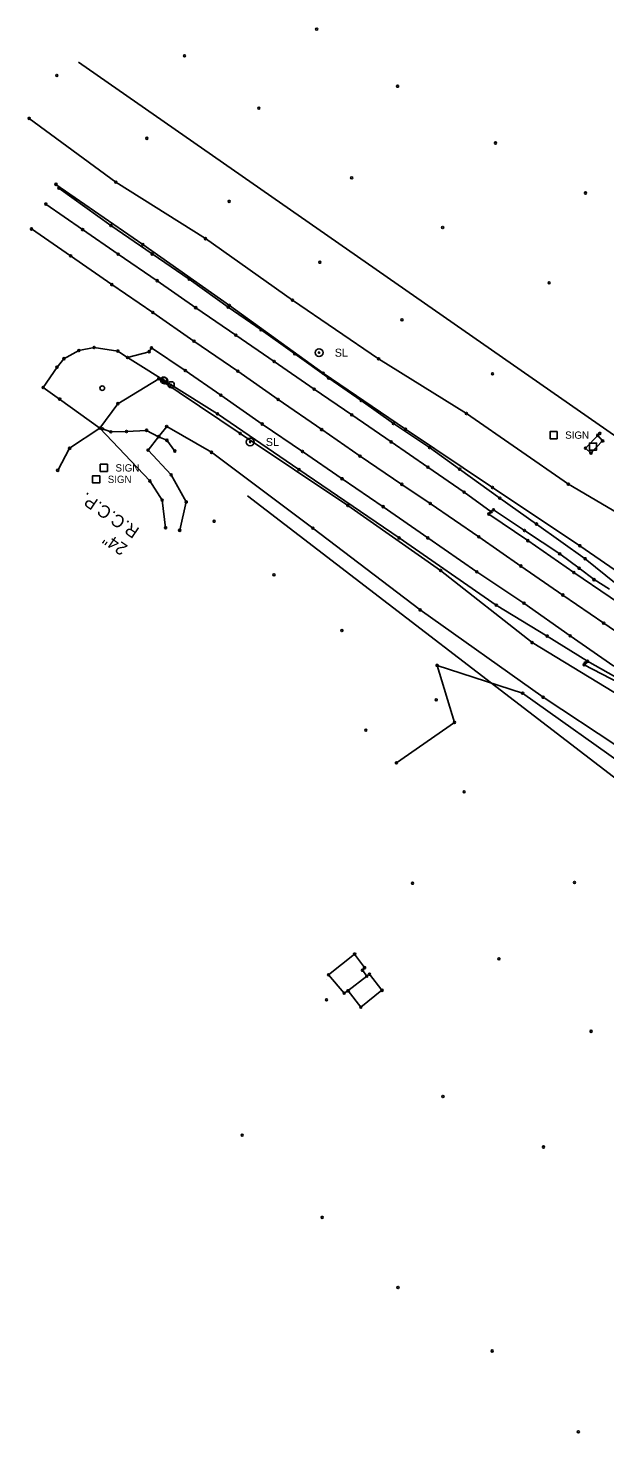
# Model space of a CAD drawing. Extents: x 15502398 to 15534190, y 8766930 to 8782112.
# Drawn here: x 15514537 to 15514815, y 8778797 to 8779472 of the extents above; entities that cross this region are included whole.
import ezdxf

# ---------------------------------------------------------------- set-up
doc = ezdxf.new("R2010")
doc.units = 0
for name, color, linetype in [('Default', 7, 'Continuous'), ('dsnCellElements', 7, 'Continuous'), ('EXT_BL', 7, 'Continuous'), ('EXT_C', 7, 'Continuous'), ('EXT_D', 7, 'Continuous'), ('EXT_EP', 7, 'Continuous'), ('EXT_SH', 7, 'Continuous'), ('EXT_SNP', 7, 'Continuous'), ('Fence', 7, 'Continuous'), ('Natural', 7, 'Continuous'), ('SurControl', 7, 'Continuous'), ('SurPointsNonDTM', 7, 'Continuous'), ('SurRoadPoints', 7, 'Continuous'), ('SurSurveyPoints', 7, 'Continuous'), ('Text', 7, 'Continuous')]:
    doc.layers.add(name, color=color, linetype=linetype)

msp = doc.modelspace()

# ---------------------------------------------------------------- linework, layer by layer
at = {"layer": 'Default'}
for p, q in [((15514602.6, 8779303.23), (15514602.6, 8779303.23)), ((15514603.07, 8779302.94), (15514603.07, 8779302.94)), ((15514606.2, 8779300.99), (15514606.2, 8779300.99)), ((15514680.96, 8779015.24), (15514680.96, 8779015.24))]:
    msp.add_line(p, q, dxfattribs=at)
msp.add_lwpolyline([(15514805.39, 8779167.3), (15514804.8, 8779166.43), (15514817.44, 8779159.8), (15514834.09, 8779151.41), (15514850.59, 8779142.29), (15514866.26, 8779132.25), (15514876.21, 8779125.21)], dxfattribs=at)
at = {"layer": 'dsnCellElements'}
for centre, radius in [((15514677.34, 8779316.44), 1.88), ((15514677.34, 8779316.44), 0.314), ((15514644.18, 8779273.47), 1.88), ((15514644.18, 8779273.47), 0.314)]:
    msp.add_circle(centre, radius, dxfattribs=at)
at = {"layer": 'EXT_BL'}
for points in [[(15514537.87, 8779429.04), (15514579.54, 8779398.37), (15514622.66, 8779371.23), (15514664.5, 8779341.66), (15514705.97, 8779313.45), (15514748.18, 8779287.18), (15514797.21, 8779253.2), (15514839.32, 8779228.6)], [(15514853.31, 8779188.82), (15514802.74, 8779223.63), (15514760.78, 8779251.63), (15514718.91, 8779279.58), (15514679.29, 8779306.58), (15514634.17, 8779339.1), (15514592.6, 8779368.4), (15514550.78, 8779397.34)], [(15514603.51, 8779232.29), (15514601.83, 8779245.57), (15514595.97, 8779254.75), (15514571.89, 8779280.15), (15514580.49, 8779291.91), (15514600.21, 8779303.93), (15514639.34, 8779277.58), (15514691.14, 8779242.93), (15514735.8, 8779211.77), (15514779.77, 8779177.06), (15514822.79, 8779150.92), (15514868.05, 8779125.45), (15514870.51, 8779121.99), (15514877.23, 8779120.79), (15514891.1, 8779108.56)], [(15514891.1, 8779108.56), (15514871.59, 8779095.57), (15514820.49, 8779127.42), (15514785.11, 8779150.78), (15514725.93, 8779192.76), (15514674.35, 8779232.07), (15514625.56, 8779268.53), (15514604.03, 8779280.96), (15514600.16, 8779276.05), (15514595.07, 8779269.61), (15514606.22, 8779257.75), (15514613.46, 8779244.67), (15514610.28, 8779231.05)]]:
    msp.add_lwpolyline(points, dxfattribs=at)
at = {"layer": 'EXT_C'}
msp.add_lwpolyline([(15514539.01, 8779375.88), (15514557.84, 8779363.02), (15514577.62, 8779349.14), (15514597.39, 8779335.77), (15514617.16, 8779321.93), (15514638.22, 8779307.5), (15514657.64, 8779293.96), (15514678.58, 8779279.44), (15514697.02, 8779266.72), (15514717.08, 8779253.14), (15514730.81, 8779243.96), (15514754.17, 8779227.88), (15514774.39, 8779213.87), (15514794.54, 8779199.93), (15514814.21, 8779186.39), (15514834.36, 8779172.7), (15514846.98, 8779164.09), (15514854.64, 8779158.75), (15514865.69, 8779151.27), (15514871.23, 8779147.78), (15514879.54, 8779141.8), (15514887.9, 8779135.92)], dxfattribs=at)
at = {"layer": 'EXT_D'}
for p, q in [((15514561.56, 8779456.11), (15514924.72, 8779203.17)), ((15514642.88, 8779247.59), (15514860.95, 8779080.15))]:
    msp.add_line(p, q, dxfattribs=at)
msp.add_lwpolyline([(15514573.08, 8779279.83), (15514577.13, 8779278.38), (15514584.72, 8779278.52), (15514594.37, 8779279.09), (15514600.16, 8779276.05), (15514604.16, 8779274.3), (15514607.96, 8779269.16)], dxfattribs=at)
at = {"layer": 'EXT_EP'}
for points in [[(15514551.61, 8779259.87), (15514557.35, 8779270.45), (15514571.89, 8779280.15), (15514552.55, 8779294.13), (15514544.64, 8779299.65), (15514551.28, 8779309.46), (15514554.61, 8779313.54), (15514561.8, 8779317.44), (15514569.11, 8779318.9), (15514580.52, 8779317.21), (15514585.22, 8779314.14), (15514595.59, 8779316.9), (15514596.7, 8779318.7), (15514612.99, 8779307.82), (15514630.07, 8779295.99), (15514649.98, 8779282.13), (15514669.32, 8779268.92), (15514688.36, 8779255.84), (15514708.12, 8779242.4), (15514729.61, 8779227.37), (15514753.2, 8779211.08), (15514775.87, 8779195.98), (15514798.13, 8779180.33), (15514819.06, 8779165.74)], [(15514853.3, 8779174.1), (15514834.8, 8779187), (15514799.88, 8779210.74), (15514777.73, 8779226.07), (15514758.94, 8779238.88), (15514760.07, 8779239.95)]]:
    msp.add_lwpolyline(points, dxfattribs=at)
for points in [[(15514805.45, 8779270.51), (15514808.09, 8779268.19), (15514813.7, 8779274), (15514811.34, 8779276.68)], [(15514691.18, 8779009.67), (15514689.36, 8779008.52), (15514681.9, 8779017.41), (15514694.44, 8779027.36), (15514699.23, 8779020.83), (15514698.17, 8779019.56), (15514700.28, 8779016.7)]]:
    msp.add_lwpolyline(points, close=True, dxfattribs=at)
at = {"layer": 'EXT_SH'}
msp.add_lwpolyline([(15514545.88, 8779387.87), (15514563.61, 8779375.58), (15514580.7, 8779363.79), (15514599.49, 8779351.03), (15514617.98, 8779338.05), (15514637.28, 8779324.87), (15514655.74, 8779312.18), (15514674.98, 8779298.9), (15514693.03, 8779286.57), (15514711.99, 8779273.52), (15514729.68, 8779261.35), (15514747.07, 8779249.4), (15514760.07, 8779239.95), (15514761.23, 8779240.9), (15514776.09, 8779230.94), (15514793.04, 8779219.72), (15514802.41, 8779212.79), (15514809.56, 8779207.33), (15514816.96, 8779202.78)], dxfattribs=at)
at = {"layer": 'EXT_SNP'}
for points in [[(15514833.52, 8779191.48), (15514834.93, 8779192.95), (15514820.27, 8779205.37), (15514805.27, 8779217.39), (15514781.85, 8779234.07), (15514764.2, 8779246.53), (15514744.94, 8779260.41), (15514730.51, 8779270.81), (15514713.07, 8779282.38), (15514697.61, 8779293.4), (15514681.94, 8779304.22), (15514665.61, 8779315.83), (15514649.42, 8779327.4), (15514633.57, 8779338.27), (15514614.88, 8779351.74), (15514597.04, 8779363.87), (15514577.23, 8779377.53), (15514552.21, 8779395.47)], [(15514838.9, 8779152.76), (15514836.55, 8779151.38), (15514822.56, 8779158.95), (15514806.37, 8779168.07), (15514787.02, 8779180.21), (15514762.57, 8779195.1), (15514715.8, 8779227.37), (15514667.65, 8779260.24), (15514628.46, 8779287.04), (15514585.22, 8779314.14)]]:
    msp.add_lwpolyline(points, dxfattribs=at)
at = {"layer": 'Fence'}
msp.add_lwpolyline([(15514701.56, 8779017.71), (15514707.58, 8779009.94), (15514697.44, 8779001.82), (15514691.39, 8779009.72)], dxfattribs=at)
at = {"layer": 'Natural'}
msp.add_lwpolyline([(15514714.5, 8779119.23), (15514742.47, 8779138.72), (15514734.07, 8779166.12), (15514775.23, 8779152.76), (15514828.83, 8779114.63), (15514870.83, 8779086.34), (15514918.03, 8779051.7), (15514929.61, 8779051.74), (15514945.58, 8779038.12), (15514983.06, 8779009.89), (15515036.69, 8778970.82), (15515087.59, 8778922.26), (15515066.58, 8778890.05)], dxfattribs=at)
at = {"layer": 'SurControl'}
msp.add_circle((15514573.04, 8779299.37), 1.12, dxfattribs=at)
at = {"layer": 'SurPointsNonDTM'}
for centre in [(15514734.07, 8779166.12), (15514804.8, 8779166.43), (15514805.39, 8779167.3), (15514775.23, 8779152.76), (15514742.47, 8779138.72), (15514714.5, 8779119.23), (15514701.56, 8779017.71), (15514691.39, 8779009.72), (15514707.58, 8779009.94), (15514697.44, 8779001.82)]:
    msp.add_circle(centre, 0.5, dxfattribs=at)
at = {"layer": 'SurRoadPoints'}
for points in [[(15514790.11, 8779275.08), (15514790.11, 8779275.08), (15514791.82, 8779275.08), (15514791.82, 8779278.51), (15514788.4, 8779278.51), (15514788.4, 8779275.08), (15514790.11, 8779275.08)], [(15514809.08, 8779269.59), (15514809.08, 8779269.59), (15514810.79, 8779269.59), (15514810.79, 8779273.01), (15514807.36, 8779273.01), (15514807.36, 8779269.59), (15514809.07, 8779269.59)], [(15514573.82, 8779259.34), (15514573.82, 8779259.34), (15514575.53, 8779259.34), (15514575.53, 8779262.77), (15514572.11, 8779262.77), (15514572.11, 8779259.34), (15514573.82, 8779259.34)], [(15514570.1, 8779253.83), (15514570.1, 8779253.83), (15514571.81, 8779253.83), (15514571.81, 8779257.25), (15514568.38, 8779257.25), (15514568.38, 8779253.83), (15514570.1, 8779253.83)]]:
    msp.add_lwpolyline(points, dxfattribs=at)
for centre, radius in [((15514602.6, 8779303.23), 1.5), ((15514603.07, 8779302.94), 1.5), ((15514602.6, 8779303.23), 0.25), ((15514603.07, 8779302.94), 0.25), ((15514606.2, 8779300.99), 1.5), ((15514606.2, 8779300.99), 0.25)]:
    msp.add_circle(centre, radius, dxfattribs=at)
at = {"layer": 'SurSurveyPoints'}
for centre in [(15514676.18, 8779471.94), (15514612.64, 8779459.14), (15514551.21, 8779449.69), (15514715.09, 8779444.47), (15514648.34, 8779433.96), (15514537.87, 8779429.04), (15514594.46, 8779419.46), (15514762.19, 8779417.21), (15514550.78, 8779397.34), (15514579.54, 8779398.37), (15514693.01, 8779400.45), (15514552.21, 8779395.47), (15514805.48, 8779393.17), (15514545.88, 8779387.87), (15514634.08, 8779389.15), (15514577.23, 8779377.53), (15514539.01, 8779375.88), (15514563.61, 8779375.58), (15514622.66, 8779371.23), (15514736.78, 8779376.61), (15514580.7, 8779363.79), (15514592.6, 8779368.4), (15514597.04, 8779363.87), (15514557.84, 8779363.02), (15514677.69, 8779359.88), (15514599.49, 8779351.03), (15514614.88, 8779351.74), (15514787.95, 8779350.04), (15514577.62, 8779349.14), (15514617.98, 8779338.05), (15514633.57, 8779338.27), (15514634.17, 8779339.1), (15514664.5, 8779341.66), (15514597.39, 8779335.77), (15514717.21, 8779332.22), (15514637.28, 8779324.87), (15514649.42, 8779327.4), (15514561.8, 8779317.44), (15514569.11, 8779318.9), (15514580.52, 8779317.21), (15514595.59, 8779316.9), (15514596.7, 8779318.7), (15514617.16, 8779321.93), (15514554.61, 8779313.54), (15514585.22, 8779314.14), (15514585.22, 8779314.14), (15514655.74, 8779312.18), (15514665.61, 8779315.83), (15514705.97, 8779313.45), (15514551.28, 8779309.46), (15514600.21, 8779303.93), (15514612.99, 8779307.82), (15514638.22, 8779307.5), (15514679.29, 8779306.58), (15514681.94, 8779304.22), (15514760.76, 8779306.29), (15514544.64, 8779299.65), (15514630.07, 8779295.99), (15514674.98, 8779298.9), (15514552.55, 8779294.13), (15514580.49, 8779291.91), (15514657.64, 8779293.96), (15514697.61, 8779293.4), (15514628.46, 8779287.04), (15514693.03, 8779286.57), (15514748.18, 8779287.18), (15514571.89, 8779280.15), (15514571.89, 8779280.15), (15514573.08, 8779279.83), (15514577.13, 8779278.38), (15514584.72, 8779278.52), (15514594.37, 8779279.09), (15514600.16, 8779276.05), (15514600.16, 8779276.05), (15514604.03, 8779280.96), (15514639.34, 8779277.58), (15514649.98, 8779282.13), (15514678.58, 8779279.44), (15514713.07, 8779282.38), (15514718.91, 8779279.58), (15514811.34, 8779276.68), (15514812.38, 8779277.63), (15514557.35, 8779270.45), (15514595.07, 8779269.61), (15514604.16, 8779274.3), (15514607.96, 8779269.16), (15514711.99, 8779273.52), (15514730.51, 8779270.81), (15514805.45, 8779270.51), (15514805.45, 8779270.51), (15514813.7, 8779274), (15514625.56, 8779268.53), (15514669.32, 8779268.92), (15514697.02, 8779266.72), (15514808.09, 8779268.19), (15514551.61, 8779259.87), (15514606.22, 8779257.75), (15514667.65, 8779260.24), (15514688.36, 8779255.84), (15514729.68, 8779261.35), (15514744.94, 8779260.41), (15514595.97, 8779254.75), (15514717.08, 8779253.14), (15514747.07, 8779249.4), (15514760.78, 8779251.63), (15514797.21, 8779253.2), (15514601.83, 8779245.57), (15514613.46, 8779244.67), (15514691.14, 8779242.93), (15514708.12, 8779242.4), (15514730.81, 8779243.96), (15514764.2, 8779246.53), (15514626.83, 8779235.39), (15514758.94, 8779238.88), (15514760.07, 8779239.95), (15514760.07, 8779239.95), (15514761.23, 8779240.9), (15514603.51, 8779232.29), (15514610.28, 8779231.05), (15514674.35, 8779232.07), (15514776.09, 8779230.94), (15514781.85, 8779234.07), (15514715.8, 8779227.37), (15514729.61, 8779227.37), (15514754.17, 8779227.88), (15514777.73, 8779226.07), (15514802.74, 8779223.63), (15514793.04, 8779219.72), (15514805.27, 8779217.39), (15514655.65, 8779209.64), (15514735.8, 8779211.77), (15514753.2, 8779211.08), (15514774.39, 8779213.87), (15514799.88, 8779210.74), (15514802.41, 8779212.79), (15514809.56, 8779207.33), (15514762.57, 8779195.1), (15514775.87, 8779195.98), (15514794.54, 8779199.93), (15514725.93, 8779192.76), (15514688.32, 8779182.86), (15514814.21, 8779186.39), (15514779.77, 8779177.06), (15514787.02, 8779180.21), (15514798.13, 8779180.33), (15514806.37, 8779168.07), (15514733.69, 8779149.58), (15514785.11, 8779150.78), (15514699.83, 8779134.96), (15514747.06, 8779105.34), (15514722.3, 8779061.38), (15514800.15, 8779061.8), (15514694.44, 8779027.36), (15514698.17, 8779019.56), (15514699.23, 8779020.83), (15514763.83, 8779025.02), (15514681.9, 8779017.41), (15514700.28, 8779016.7), (15514689.36, 8779008.52), (15514691.18, 8779009.67), (15514691.18, 8779009.67), (15514680.94, 8779005.38), (15514808.13, 8778990.21), (15514736.92, 8778958.91), (15514640.31, 8778940.31), (15514785.23, 8778934.61), (15514678.83, 8778900.79), (15514715.29, 8778867.08), (15514760.59, 8778836.57), (15514802.03, 8778797.69)]:
    msp.add_circle(centre, 0.5, dxfattribs=at)

# ---------------------------------------------------------------- texts
at = {"layer": 'dsnCellElements'}
for p in [(15514684.88, 8779314.51), (15514651.72, 8779271.55)]:
    msp.add_text('SL', height=3.847, dxfattribs=at).set_placement(p)
at = {"layer": 'SurRoadPoints'}
for p in [(15514795.71, 8779275.05), (15514579.42, 8779259.31), (15514575.7, 8779253.79)]:
    msp.add_text('SIGN', height=3.498, dxfattribs=at).set_placement(p)
at = {"layer": 'Text'}
for s, p in [('R.C.C.P.', (15514591.34, 8779231.71)), ('24"', (15514585.67, 8779223.47))]:
    msp.add_text(s, height=6, rotation=145.49226, dxfattribs=at).set_placement(p)

doc.saveas('drawing.dxf')
